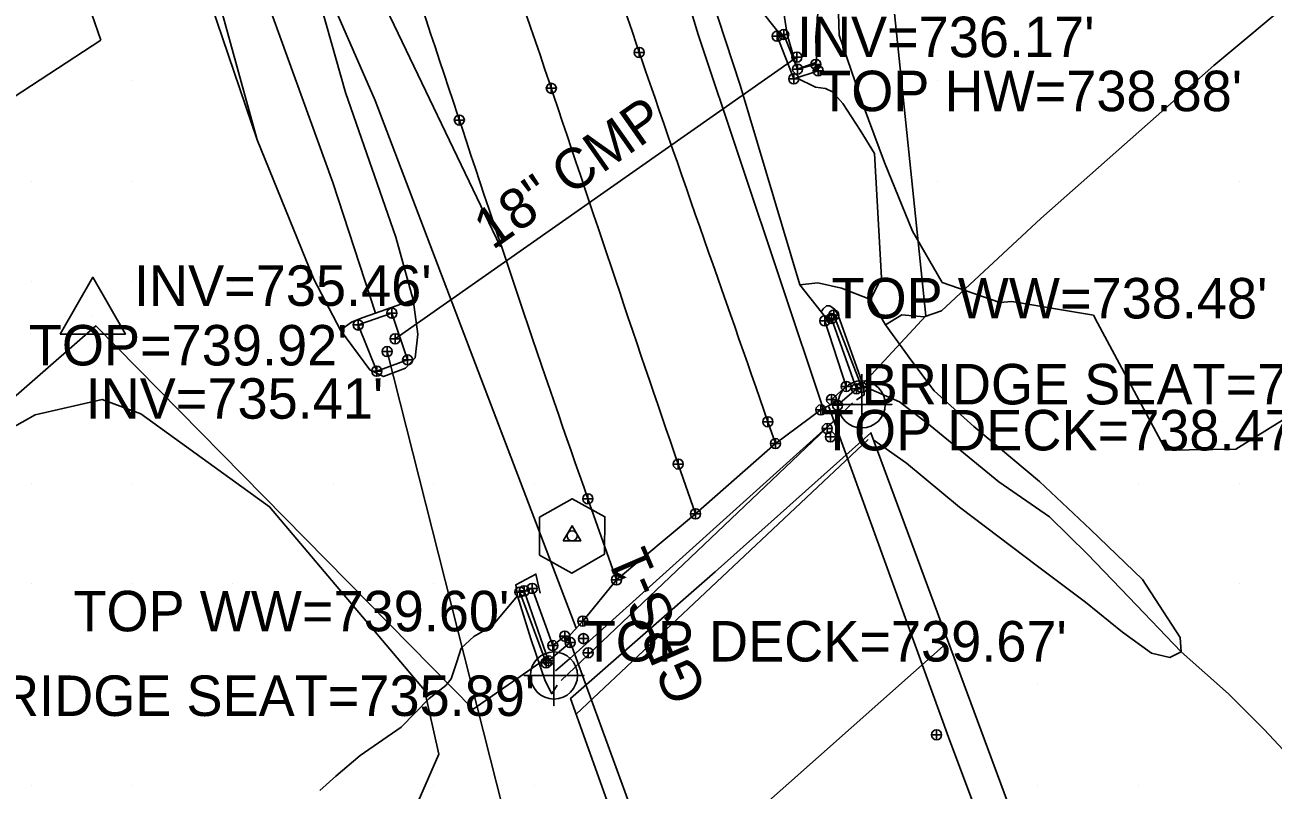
# Model space of a CAD drawing. Extents: x 1548934 to 1561348, y 809680 to 824075.
# Drawn here: x 1551709.4 to 1551833.4, y 810839.5 to 810915.5 of the extents above; entities that cross this region are included whole.
import ezdxf

# ---------------------------------------------------------------- set-up
doc = ezdxf.new("R2010")
doc.units = 0
for name, color, linetype in [('_CIVIL_CONSTRUCTION', 7, 'Continuous'), ('Default', 7, 'Continuous'), ('Draft_Profile_Labels', 7, 'Continuous'), ('E_NCDOT_Vertical_Profile_Ground_Line', 7, 'Continuous'), ('Exist DTM QL2 LIDAR Elevation Point', 7, 'Continuous'), ('Exist Guardrail', 7, 'Continuous'), ('Exist Other Culture Area Outline', 7, 'Continuous'), ('Exist Structure Major Bridge Seat Text', 7, 'Continuous'), ('Exist Structure Major Bridge Seat Top Elevation', 7, 'Continuous'), ('Exist Structure Major Bridge WW Text', 7, 'Continuous'), ('Exist Structure Major Deck Tunnel Box Culvert', 7, 'Continuous'), ('Exist Structure Major Deck Tunnel Box Culvert Text', 7, 'Continuous'), ('Exist Structure Minor Catch Basin Top Elevation', 7, 'Continuous'), ('Exist Structure Minor Head and End Wall Text', 7, 'Continuous'), ('Exist Structure Minor Pipes CMP 18 Inch Invert Elevation', 7, 'Continuous'), ('Exist Structure Minor Pipes CMP 18 Inch Size Material Text', 7, 'Continuous'), ('Exist Vegetation Woods Line', 7, 'Continuous'), ('P_NCDOT_Horizontal_Alignment', 7, 'Continuous'), ('P_NCDOT_Horizontal_Alignment_Station_Label', 7, 'Continuous'), ('P_NCDOT_Vertical_Profile_Grade', 7, 'Continuous'), ('P_NCDOT_Vertical_Profile_Grade_Minor_Road', 7, 'Continuous'), ('P_RDY_Concrete_Barrier', 7, 'Continuous'), ('P_RDY_Dimension_Text', 7, 'Continuous'), ('P_RDY_Guardrail_Attenuator_Cell', 7, 'Continuous'), ('P_RDY_Paved_Shoulder', 7, 'Continuous'), ('P_RDY_Terminator_Cell', 7, 'Continuous'), ('PH Exist DTM Breakline', 7, 'Continuous'), ('Scratch_Level_6', 7, 'Continuous')]:
    doc.layers.add(name, color=color, linetype=linetype)

# ---------------------------------------------------------------- blocks, each defined once
blk = doc.blocks.new('SurveyPointCell')
at = {"layer": 'Default'}
for p, q in [((-0.5, 0), (0.5, 0)), ((0, -0.5), (0, 0.5))]:
    blk.add_line(p, q, dxfattribs=at)
blk.add_circle((0, 0), 0.5, dxfattribs=at)

msp = doc.modelspace()

# ---------------------------------------------------------------- linework, layer by layer
at = {"layer": '_CIVIL_CONSTRUCTION'}
msp.add_line((1551763.72, 810864.75), (1551763.72, 810864.75), dxfattribs=at)
msp.add_line((1551763.72, 810864.75), (1551763.72, 810864.75), dxfattribs=at)
msp.add_line((1551763.72, 810864.75), (1551763.72, 810864.75), dxfattribs=at)
msp.add_lwpolyline([(1551760.49, 810866.62), (1551763.74, 810868.43), (1551766.99, 810866.65), (1551766.94, 810862.92), (1551763.69, 810861.03), (1551760.49, 810862.85)], close=True, dxfattribs=at)
msp.add_lwpolyline([(1551760.49, 810866.62), (1551763.74, 810868.43), (1551766.99, 810866.65), (1551766.94, 810862.92), (1551763.69, 810861.03), (1551760.49, 810862.85)], close=True, dxfattribs=at)
msp.add_lwpolyline([(1551760.49, 810866.62), (1551763.74, 810868.43), (1551766.99, 810866.65), (1551766.94, 810862.92), (1551763.69, 810861.03), (1551760.49, 810862.85)], close=True, dxfattribs=at)
at = {"layer": 'Draft_Profile_Labels'}
for p, q in [((1551789.81, 810878.01), (1551788.44, 810877.26)), ((1551764.78, 810856.29), (1551763.2, 810854.55))]:
    msp.add_line(p, q, dxfattribs=at)
for points in [[(1551790.09, 810877.72), (1551791.97, 810879.37), (1551789.49, 810886.35), (1551788.83, 810886.11), (1551790.96, 810879.6), (1551789.5, 810878.31)], [(1551763.52, 810854.16), (1551761.37, 810852.33), (1551758.96, 810859.29), (1551759.76, 810859.53), (1551761.8, 810853.85), (1551762.99, 810854.8)]]:
    msp.add_lwpolyline(points, close=True, dxfattribs=at)
msp.add_lwpolyline([(1551764.78, 810856.29), (1551768.13, 810860.38), (1551775.98, 810866.94), (1551783.92, 810873.92), (1551788.44, 810877.26)], dxfattribs=at)
at = {"layer": 'E_NCDOT_Vertical_Profile_Ground_Line'}
for p, q in [((1551716.1, 810886.69), (1551716.1, 810886.69)), ((1551783.17, 810876.09), (1551783.92, 810873.92)), ((1551765.29, 810868.44), (1551768.13, 810860.38))]:
    msp.add_line(p, q, dxfattribs=at)
msp.add_lwpolyline([(1551712.86, 810884.8), (1551716.11, 810890.44), (1551719.35, 810884.8)], close=True, dxfattribs=at)
for points in [[(1551669.23, 811277), (1551672.74, 811263.65), (1551679.61, 811234.97), (1551690.37, 811191.22), (1551702.41, 811145.66), (1551714.33, 811100.03), (1551727, 811053.45), (1551740.47, 811006.5), (1551755.13, 810959.34), (1551769.1, 810915.85), (1551778.93, 810888.33), (1551783.17, 810876.09)], [(1551650.09, 811272.18), (1551653.54, 811258.38), (1551661.25, 811229.55), (1551671.78, 811185.41), (1551683.85, 811140.03), (1551696.07, 811094.56), (1551708.62, 811047.91), (1551722.36, 811000.57), (1551736.98, 810952.93), (1551751.55, 810908.96), (1551760.88, 810880.92), (1551765.29, 810868.44)]]:
    msp.add_open_spline(points, degree=3, dxfattribs=at)
at = {"layer": 'Exist DTM QL2 LIDAR Elevation Point'}
for p, q in [((1551710, 810910), (1551710, 810910)), ((1551720, 810910), (1551720, 810910)), ((1551800, 810910), (1551800, 810910)), ((1551810, 810910), (1551810, 810910)), ((1551710, 810900), (1551710, 810900)), ((1551720, 810900), (1551720, 810900)), ((1551800, 810900), (1551800, 810900)), ((1551830.01, 810900), (1551830.01, 810900)), ((1551710, 810890), (1551710, 810890)), ((1551720, 810890), (1551720, 810890)), ((1551730, 810890), (1551730, 810890)), ((1551820, 810890), (1551820, 810890)), ((1551830.01, 810890), (1551830.01, 810890)), ((1551710, 810880), (1551710, 810880)), ((1551720, 810880), (1551720, 810880)), ((1551730, 810880), (1551730, 810880)), ((1551810, 810880), (1551810, 810880)), ((1551820, 810880), (1551820, 810880)), ((1551830.01, 810880), (1551830.01, 810880)), ((1551710, 810870), (1551710, 810870)), ((1551720, 810870), (1551720, 810870)), ((1551730, 810870), (1551730, 810870)), ((1551740, 810870), (1551740, 810870)), ((1551750, 810870), (1551750, 810870)), ((1551760, 810870), (1551760, 810870)), ((1551820, 810870), (1551820, 810870)), ((1551830.01, 810870), (1551830.01, 810870)), ((1551710, 810860), (1551710, 810860)), ((1551720, 810860), (1551720, 810860)), ((1551730, 810860), (1551730, 810860)), ((1551740, 810860), (1551740, 810860)), ((1551750, 810860), (1551750, 810860)), ((1551830.01, 810860), (1551830.01, 810860)), ((1551710, 810850), (1551710, 810850)), ((1551720, 810850), (1551720, 810850)), ((1551730, 810850), (1551730, 810850)), ((1551740, 810850), (1551740, 810850)), ((1551810, 810850), (1551810, 810850)), ((1551710, 810840), (1551710, 810840)), ((1551720, 810840), (1551720, 810840)), ((1551750, 810840), (1551750, 810840)), ((1551760, 810840), (1551760, 810840)), ((1551810, 810840), (1551810, 810840)), ((1551820, 810840), (1551820, 810840))]:
    msp.add_line(p, q, dxfattribs=at)
at = {"layer": 'Exist Guardrail'}
for points in [[(1551747.29, 811039.69), (1551755.45, 810993.12), (1551761.38, 810965.78), (1551767.15, 810944.71), (1551776.25, 810914.57), (1551788.66, 810877.39)], [(1551764.14, 810855.59), (1551754.13, 810881.81), (1551744.16, 810908), (1551735.65, 810927.52), (1551722.54, 810953.77), (1551715.12, 810967.41)]]:
    msp.add_lwpolyline(points, dxfattribs=at)
at = {"layer": 'Exist Other Culture Area Outline'}
for p, q in [((1551700.72, 810960.62), (1551716.92, 810914)), ((1551716.92, 810914), (1551644.86, 810866.94))]:
    msp.add_line(p, q, dxfattribs=at)
at = {"layer": 'Exist Structure Major Deck Tunnel Box Culvert'}
for points in [[(1551890.16, 810628.77), (1551869.49, 810674.52), (1551854.07, 810710.39), (1551839.84, 810744.54), (1551817.23, 810801.67), (1551801.12, 810844.76), (1551789.24, 810877.58)], [(1551763.35, 810854.68), (1551776.07, 810819.84), (1551783.15, 810800.69), (1551795.34, 810769.16), (1551805.49, 810743.34), (1551817.59, 810713.87), (1551830.15, 810684.6), (1551846.39, 810647.48), (1551862.11, 810612.89), (1551864.95, 810606.9)]]:
    msp.add_lwpolyline(points, dxfattribs=at)
at = {"layer": 'Exist Vegetation Woods Line'}
for points in [[(1551842.25, 810881.19), (1551829.67, 810873.37), (1551822.69, 810873.27), (1551815.92, 810885.9), (1551815.5, 810886.67), (1551807.41, 810888.02), (1551806.22, 810887.92), (1551800.5, 810889.93), (1551797.54, 810895.02), (1551794.74, 810901.84), (1551792.64, 810907.53), (1551790.26, 810914.5), (1551790.13, 810918.88), (1551789.49, 810924.31), (1551789.81, 810930.06), (1551791.28, 810939.57), (1551792.61, 810944.6), (1551793.56, 810968.12), (1551792.97, 810978.75), (1551794.6, 810986.48), (1551800.37, 810995.02), (1551809.38, 810998.56), (1551832.14, 811006.96)], [(1551659.01, 810830.79), (1551687.27, 810857.87), (1551694.83, 810866.1), (1551701.31, 810871.68), (1551710.4, 810876.77), (1551717.05, 810878.29), (1551720.9, 810876.86), (1551733.67, 810867.65), (1551749.06, 810849.43), (1551750.48, 810843.05), (1551748.42, 810838.37)]]:
    msp.add_lwpolyline(points, dxfattribs=at)
at = {"layer": 'P_NCDOT_Horizontal_Alignment'}
msp.add_line((1551763.72, 810864.75), (1551763.72, 810864.75), dxfattribs=at)
msp.add_line((1551763.72, 810864.75), (1551763.72, 810864.75), dxfattribs=at)
msp.add_line((1551763.72, 810864.75), (1551763.72, 810864.75), dxfattribs=at)
msp.add_lwpolyline([(1551762.85, 810864.25), (1551763.72, 810865.75), (1551764.58, 810864.25)], close=True, dxfattribs=at)
msp.add_lwpolyline([(1551762.85, 810864.25), (1551763.72, 810865.75), (1551764.58, 810864.25)], close=True, dxfattribs=at)
msp.add_lwpolyline([(1551762.85, 810864.25), (1551763.72, 810865.75), (1551764.58, 810864.25)], close=True, dxfattribs=at)
msp.add_circle((1551763.72, 810864.75), 0.5, dxfattribs=at)
msp.add_circle((1551763.72, 810864.75), 0.5, dxfattribs=at)
msp.add_circle((1551763.72, 810864.75), 0.5, dxfattribs=at)
at = {"layer": 'P_NCDOT_Horizontal_Alignment_Station_Label'}
for points in [[(1551792.49, 810880.81), (1551792.49, 810874.81), (1551792.49, 810877.81), (1551795.49, 810877.81), (1551789.49, 810877.81)], [(1551761.92, 810853.87), (1551761.92, 810847.88), (1551761.92, 810850.88), (1551764.92, 810850.88), (1551758.92, 810850.88)]]:
    msp.add_lwpolyline(points, dxfattribs=at)
for centre in [(1551792.49, 810877.81), (1551761.92, 810850.88)]:
    msp.add_circle(centre, 2.34, dxfattribs=at)
at = {"layer": 'P_NCDOT_Vertical_Profile_Grade'}
msp.add_lwpolyline([(1551747.39, 810882.23), (1551745.83, 810886.87), (1551742.47, 810885.7), (1551744.32, 810881.11)], close=True, dxfattribs=at)
at = {"layer": 'P_NCDOT_Vertical_Profile_Grade_Minor_Road'}
msp.add_line((1551775.98, 810866.94), (1551774.27, 810871.88), dxfattribs=at)
msp.add_open_spline([(1551774.27, 810871.88), (1551769.96, 810884.28), (1551760.75, 810912.23), (1551745.66, 810955.91), (1551731.5, 811003.54), (1551718, 811050.78), (1551705.43, 811097.26), (1551693.24, 811142.66), (1551681.43, 811187.98), (1551670.2, 811231.95), (1551663.06, 811260.98), (1551659.56, 811274.89)], degree=3, dxfattribs=at)
at = {"layer": 'P_RDY_Concrete_Barrier'}
for points in [[(1551786.05, 810912.31), (1551746.14, 810884.32)], [(1551745.35, 810883.06), (1551769.01, 810789.72)]]:
    msp.add_lwpolyline(points, dxfattribs=at)
at = {"layer": 'P_RDY_Dimension_Text'}
for points in [[(1551792.63, 810879.89), (1551798.87, 810886.61), (1551791.81, 810954.68), (1551790.16, 810983.57), (1551796.35, 810987.52), (1551966.16, 811082.82)], [(1551760.85, 810852.38), (1551753.88, 810847.55), (1551716.43, 810885.61), (1551695.29, 810867.16), (1551642.57, 810818.58), (1551625.51, 810802.67), (1551609.65, 810768.78), (1551603.27, 810753.55)]]:
    msp.add_lwpolyline(points, dxfattribs=at)
at = {"layer": 'P_RDY_Guardrail_Attenuator_Cell'}
msp.add_lwpolyline([(1551784.74, 810914.55), (1551786.12, 810911.12), (1551787.94, 810911.59), (1551788.17, 810910.96), (1551785.74, 810910.15), (1551784.09, 810914.38)], close=True, dxfattribs=at)
at = {"layer": 'P_RDY_Paved_Shoulder'}
msp.add_lwpolyline([(1551780.34, 810801.61), (1551763.58, 810848.6), (1551777.95, 810861.19), (1551793.41, 810875), (1551811.93, 810824.92)], dxfattribs=at)
at = {"layer": 'P_RDY_Terminator_Cell'}
for points in [[(1551792.5, 810879.49), (1551789.72, 810886.68)], [(1551761.14, 810852.14), (1551758.54, 810859.17)], [(1551800.59, 810853.79), (1551785.25, 810840.2), (1551771.51, 810828.03)]]:
    msp.add_lwpolyline(points, dxfattribs=at)
at = {"layer": 'PH Exist DTM Breakline'}
for p, q in [((1551787.9, 810909.33), (1551786, 810910.24)), ((1551793.13, 810874.32), (1551764.14, 810847.04))]:
    msp.add_line(p, q, dxfattribs=at)
for points in [[(1551734.17, 811060.29), (1551739.78, 811040.33), (1551746.93, 811018.26), (1551753.09, 810994.66), (1551756.45, 810990.16), (1551757.42, 810988.4), (1551757.91, 810987.38), (1551758.68, 810985.27), (1551761.52, 810976.04), (1551767.02, 810957.73), (1551771.03, 810942.69), (1551775.29, 810925.19), (1551780.42, 810909.54), (1551786.36, 810889.7)], [(1551964.87, 811011.81), (1551950.05, 811001.19), (1551928.64, 810985.19), (1551911.37, 810973.98), (1551899.79, 810966.08), (1551880.25, 810951.2), (1551869.51, 810942.95), (1551844.01, 810925.31), (1551827.48, 810911.47), (1551810.29, 810896.27), (1551800.43, 810887.11), (1551798.7, 810886.52), (1551796.47, 810886.72), (1551794.87, 810885.71)], [(1551756.6, 810893.45), (1551744.48, 810918.77), (1551737.77, 810938.57), (1551731.45, 810955.6), (1551727.45, 810965), (1551725.9, 810967.28), (1551723.52, 810969.49), (1551719.68, 810971.06), (1551716.03, 810972.06), (1551713.36, 810972.06), (1551709.28, 810971.65), (1551705.62, 810970.61), (1551696.74, 810966.37), (1551681.91, 810957.07), (1551664.96, 810944.51), (1551652.69, 810934.96), (1551641.8, 810926.1), (1551621.87, 810912.31)], [(1551744.21, 810886.86), (1551739.95, 810899.84), (1551734.01, 810916.31), (1551728.73, 810931.9), (1551723.05, 810947.61), (1551720.07, 810957.53), (1551718.47, 810963.63), (1551718.53, 810966.43)], [(1551714.79, 810964.11), (1551716, 810957.7), (1551718.68, 810949.05), (1551722.53, 810937), (1551726.88, 810924.28), (1551732.43, 810904.08)], [(1551786.01, 810911.39), (1551785.09, 810914.56), (1551784.76, 810916.72), (1551783.21, 810922.85), (1551782.22, 810925.47), (1551781.3, 810928.03), (1551780.51, 810930.17)], [(1551737.87, 810920.64), (1551741.23, 810908.78), (1551746.21, 810894.44), (1551747.92, 810888.21), (1551748.39, 810884.78), (1551748.14, 810882.44), (1551747.16, 810881.4), (1551744.98, 810880.59), (1551743.62, 810881.25), (1551740.73, 810885.18), (1551738.08, 810890.25), (1551732.43, 810904.08), (1551726.71, 810920.97)], [(1551784.48, 810914.48), (1551784.02, 810915.01), (1551782.47, 810916.99)], [(1551786.11, 810911.13), (1551787.99, 810911.81), (1551787.92, 810914.29), (1551788.2, 810917.45)], [(1551793.36, 810888.24), (1551794.47, 810890.39), (1551793.77, 810902.75), (1551792.33, 810905.06), (1551790.63, 810907.69), (1551789.59, 810908.86), (1551788.91, 810909.19), (1551787.9, 810909.33)], [(1551793.69, 810874.25), (1551796.93, 810871.97), (1551802.2, 810867.59), (1551809.97, 810861.75), (1551814.73, 810858.16), (1551818.41, 810855.17), (1551821.28, 810853.1), (1551823.11, 810852.68), (1551824.21, 810853.22), (1551824.13, 810854.64), (1551820.38, 810860.42), (1551815.23, 810865.39), (1551810.15, 810870.15), (1551803.62, 810875.62), (1551799.68, 810879.17), (1551797.47, 810882.1), (1551794.87, 810885.71), (1551793.36, 810888.24), (1551790.49, 810889.35), (1551788.13, 810889.9), (1551786.36, 810889.7), (1551788.46, 810887.01)], [(1551747.92, 810888.21), (1551746.26, 810887.6), (1551744.21, 810886.86), (1551742.88, 810886.4), (1551741.81, 810885.97), (1551740.73, 810885.18)], [(1551791.96, 810878.25), (1551792.75, 810878.76), (1551792.66, 810879.63), (1551790.15, 810886.68), (1551789.79, 810887.28), (1551789.34, 810887.59), (1551789.01, 810887.61), (1551788.67, 810887.31), (1551788.46, 810887.01), (1551789.09, 810886.2)], [(1551792.66, 810879.63), (1551796.25, 810878.06), (1551799.3, 810875.73), (1551806.11, 810870.12), (1551811.16, 810866.63), (1551814.91, 810862.94), (1551819.03, 810858.65), (1551824.21, 810853.22), (1551828.93, 810849.06), (1551832.46, 810845.53), (1551834.86, 810842.98), (1551837.31, 810839.5)], [(1551762.65, 810850.37), (1551790.33, 810876.72), (1551791.58, 810877.95)], [(1551762.09, 810851.33), (1551763.47, 810852.52), (1551790.33, 810876.72)], [(1551738.65, 810839.44), (1551740.26, 810840.89), (1551742.66, 810842.92), (1551746.73, 810845.74), (1551749.53, 810848.58), (1551751.18, 810849.9), (1551751.72, 810850.54), (1551752.27, 810852.23), (1551752.71, 810853.59), (1551753.96, 810854.77), (1551754.65, 810855.16), (1551755.84, 810855.87), (1551758.3, 810858.81), (1551758.15, 810859.89), (1551760.13, 810860.95), (1551760.55, 810859.06)], [(1551758.3, 810858.81), (1551759.62, 810854.52), (1551761.05, 810850.34), (1551761.71, 810849.06), (1551762.25, 810849.92)]]:
    msp.add_lwpolyline(points, dxfattribs=at)

# ---------------------------------------------------------------- block references
at = {"layer": 'Default'}
for p in [(1551784.09, 810914.38), (1551784.74, 810914.55), (1551770.39, 810912.78), (1551786.05, 810912.31), (1551787.94, 810911.59), (1551785.74, 810910.15), (1551786.12, 810911.12), (1551788.17, 810910.96), (1551761.66, 810909.21), (1551752.52, 810906.06), (1551745.83, 810886.87), (1551789.72, 810886.68), (1551742.47, 810885.7), (1551788.83, 810886.11), (1551789.49, 810886.35), (1551746.14, 810884.32), (1551745.35, 810883.06), (1551747.39, 810882.23), (1551744.32, 810881.11), (1551790.96, 810879.6), (1551791.97, 810879.37), (1551792.5, 810879.49), (1551789.5, 810878.31), (1551788.44, 810877.26), (1551790.09, 810877.72), (1551783.17, 810876.09), (1551789.07, 810875.41), (1551789.38, 810874.58), (1551783.92, 810873.92), (1551774.27, 810871.88), (1551765.29, 810868.44), (1551775.98, 810866.94), (1551758.96, 810859.29), (1551759.76, 810859.53), (1551768.13, 810860.38), (1551758.54, 810859.17), (1551764.78, 810856.29), (1551762.99, 810854.8), (1551764.85, 810854.54), (1551761.8, 810853.85), (1551763.52, 810854.16), (1551765.33, 810853.14), (1551761.14, 810852.14), (1551761.37, 810852.33), (1551799.93, 810844.99)]:
    msp.add_blockref('SurveyPointCell', p, dxfattribs=at)

# ---------------------------------------------------------------- texts
at = {"layer": 'Exist Structure Major Bridge Seat Text'}
msp.add_text("BRIDGE SEAT=734.83'", height=4.02, dxfattribs=at).set_placement((1551792.49, 810877.81))
at = {"layer": 'Exist Structure Major Bridge Seat Top Elevation'}
msp.add_text("BRIDGE SEAT=735.89'", height=4.02, dxfattribs=at).set_placement((1551703.31, 810846.86))
at = {"layer": 'Exist Structure Major Bridge WW Text'}
for s, p in [("TOP WW=738.48'", (1551789.49, 810886.35)), ("TOP WW=739.60'", (1551714.19, 810855.27))]:
    msp.add_text(s, height=4.02, dxfattribs=at).set_placement(p)
at = {"layer": 'Exist Structure Major Deck Tunnel Box Culvert Text'}
for s, p in [("TOP DECK=738.47'", (1551788.44, 810873.24)), ("TOP DECK=739.67'", (1551764.78, 810852.27))]:
    msp.add_text(s, height=4.02, dxfattribs=at).set_placement(p)
at = {"layer": 'Exist Structure Minor Catch Basin Top Elevation'}
msp.add_text("TOP=739.92'", height=4.02, rotation=360, dxfattribs=at).set_placement((1551709.76, 810881.68))
at = {"layer": 'Exist Structure Minor Head and End Wall Text'}
msp.add_text("TOP HW=738.88'", height=4.02, rotation=360, dxfattribs=at).set_placement((1551788.17, 810906.94))
at = {"layer": 'Exist Structure Minor Pipes CMP 18 Inch Invert Elevation'}
for s, p in [("INV=736.17'", (1551786.05, 810912.31)), ("INV=735.46'", (1551720.2, 810887.6)), ("INV=735.41'", (1551715.4, 810876.39))]:
    msp.add_text(s, height=4.02, rotation=360, dxfattribs=at).set_placement(p)
at = {"layer": 'Exist Structure Minor Pipes CMP 18 Inch Size Material Text'}
msp.add_text('18" CMP', height=4.02, rotation=35.0391, dxfattribs=at).set_placement((1551755.82, 810893.09))
at = {"layer": 'Scratch_Level_6'}
msp.add_text('GPS-1', height=4.02, rotation=113.1809, dxfattribs=at).set_placement((1551777.18, 810849.2))

doc.saveas('drawing.dxf')
